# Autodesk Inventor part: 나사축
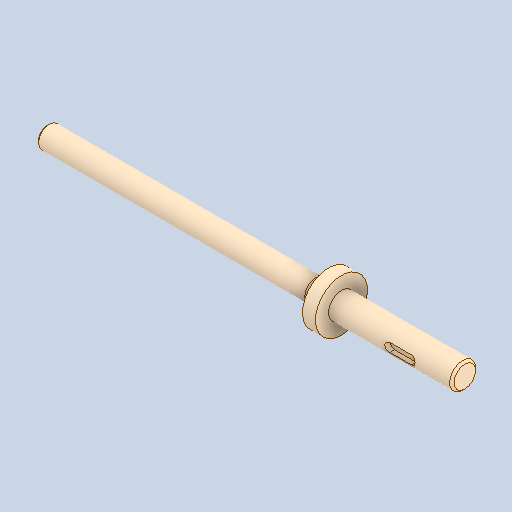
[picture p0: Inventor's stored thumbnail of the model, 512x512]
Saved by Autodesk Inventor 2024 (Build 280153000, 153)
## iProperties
Created: 2024-07
Part Number: 나사축
Material: 강철, 연강
Document SubType Name: Modeling
Designer: com
Density: 7.86 g/cm^3
Appearance: 기본값
Author: jhkim
Sending System: Autodesk Inventor 2025
Preprocessor: ST-DEVELOPER v20
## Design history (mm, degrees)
feature "솔리드1"
node "솔리드2"
